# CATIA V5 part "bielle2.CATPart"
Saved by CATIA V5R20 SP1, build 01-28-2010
Part number: Part1.1.2
Bounding box of the stored display mesh (mm): x 33 to 87, y -5 to 10, z 28.093 to 41.907
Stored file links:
  E:\EDELI\gcausse\Edeli_2012_685_gcausse\bielle2.CATPart
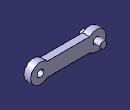
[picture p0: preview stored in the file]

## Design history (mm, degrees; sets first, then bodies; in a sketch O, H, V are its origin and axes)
Parameters
  long = 0.04
  diamtrou = 0.005
Body1 (main body)
  Sketch1 on zx-plane, origin (0, 0, 0), H (-1, 0, 0), V (0, 0, 1)
    line L1 (-44.899, 40) -> (-75.101, 40)
    line L2 (-44.899, 30) -> (-75.101, 30)
    arc A1 centre (-40, 35) radius 7 from (-44.899, 40) to (-44.899, 30) cw
    point P5 (-40, 35)
    point P6 (-35.101, 30)
    arc A2 centre (-80, 35) radius 7 from (-75.101, 40) to (-75.101, 30) ccw
    point P7 (-80, 35)
    circle A3 centre (-40, 35) radius 2.5
    distance P7 L1 = 5
    distance P5 L2 = 5
    distance L2 L1 = 10
    radius A1 = 7
    radius A2 = 7
    distance P5 P7 = 40 {= long}
    radius A3 = 2.5
    horizontal: L1 H, L2 H
    coincidence: A1 P6, P6 L2
  Pad1: profile Sketch1, direction (0, 1, 0), length 5
  Sketch2 on end face of Pad1, origin (0, 5, 0), H (-1, 0, 0), V (0, 0, 1)
    circle A1 centre (-80, 35) radius 2.5
    reference projected arc E1 centre (-80, 35) radius 7 from (-75.101, 40) to (-75.101, 30) ccw from edge [face of Pad1 from Sketch1.A2 | end face of Pad1]
    reference projected arc E2 centre (-80, 35) radius 7 from (-75.101, 40) to (-75.101, 30) ccw from edge [face of Pad1 from Sketch1.A2 | end face of Pad1]
    radius A1 = 2.5
    radius E2 = 7 (reference)
    concentricity: A1 E1
  Pocket1: profile Sketch2, direction (0, -1, 0), length 5
  DatumCurve1
  Sketch3 on end face of Pad1, origin (0, 5, 0), H (-1, 0, 0), V (0, 0, 1)
    circle A1 centre (-40, 35) radius 2.5
    reference projected arc E1 centre (-40, 35) radius 7 from (-33.8311, 31.6917) to (-43.4335, 28.8999) ccw from edge of DatumCurve1
    reference projected arc E2 centre (-40, 35) radius 7 from (-33.8311, 31.6917) to (-43.4335, 28.8999) ccw from edge of DatumCurve1
    radius A1 = 2.5
    radius E2 = 7 (reference)
    concentricity: A1 E1
  Pad2: profile Sketch3, direction (0, 1, 0), length 5, opposite side length 10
